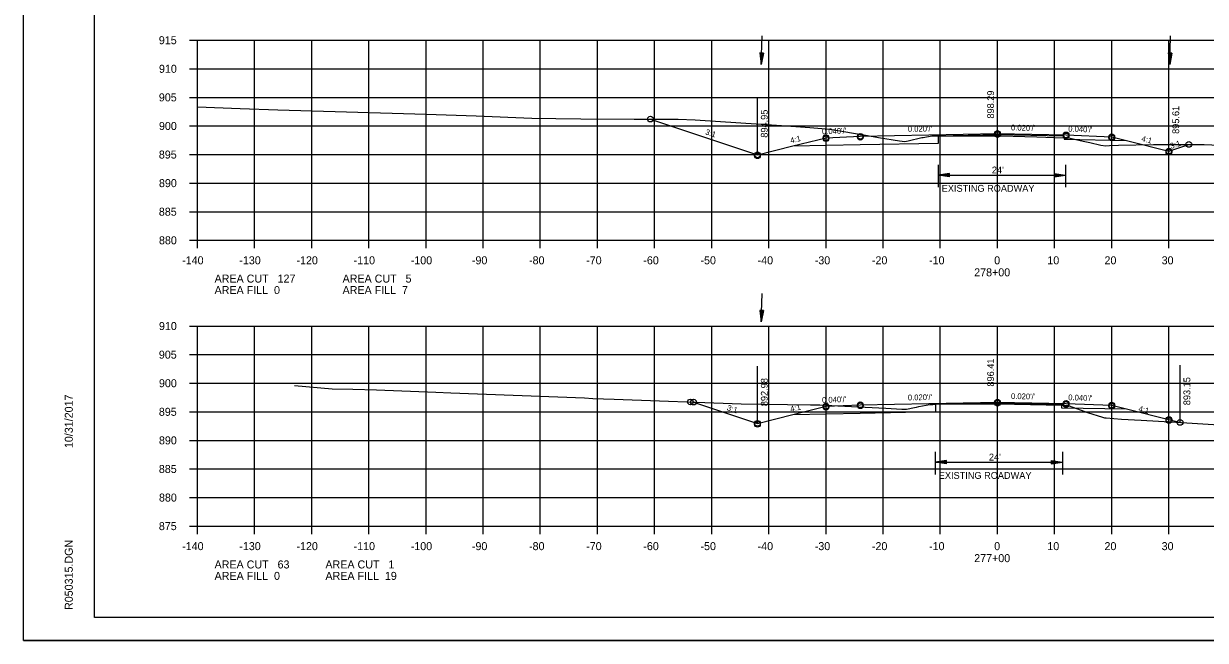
# Model space of a CAD drawing. Extents: x 1486524 to 1499135, y 326561 to 337924.
# Drawn here: x 1488812.5 to 1489019.3, y 331285.9 to 331393.8 of the extents above; entities that cross this region are included whole.
import ezdxf

# ---------------------------------------------------------------- set-up
doc = ezdxf.new("R2010")
doc.units = 0
for name, color, linetype in [('E_Const Align', 7, 'Continuous'), ('E_Const Align Station', 7, 'Continuous'), ('E_Ownership Information', 7, 'Continuous'), ('E_Property Line', 7, 'Continuous'), ('E_Proposed ROW and Easements', 7, 'Continuous'), ('E_Proposed ROW Fig Annot', 7, 'Continuous'), ('E_Quarter Calls', 7, 'Continuous'), ('E_Survey Point', 7, 'Continuous'), ('E_Title Sheet', 7, 'Continuous'), ('E_Tract Number', 7, 'Continuous'), ('R_Water Annot', 7, 'Continuous'), ('R_Xsect Elev', 7, 'Continuous'), ('R_Xsect Slope', 7, 'Continuous')]:
    doc.layers.add(name, color=color, linetype=linetype)

msp = doc.modelspace()

# ---------------------------------------------------------------- linework, layer by layer
at = {"layer": 'E_Const Align'}
for p, q in [((1488841.49, 331390.92), (1488842.89, 331390.92)), ((1488842.89, 331355.92), (1488842.89, 331390.92)), ((1488841.49, 331385.92), (1488842.89, 331385.92)), ((1488841.49, 331380.92), (1488842.89, 331380.92)), ((1488841.49, 331375.92), (1488842.89, 331375.92)), ((1488841.49, 331370.92), (1488842.89, 331370.92)), ((1488841.49, 331365.92), (1488842.89, 331365.92)), ((1488841.49, 331360.92), (1488842.89, 331360.92)), ((1488841.49, 331355.92), (1488842.89, 331355.92)), ((1488842.89, 331355.92), (1489122.89, 331355.92)), ((1488842.89, 331354.52), (1488842.89, 331355.92)), ((1488852.89, 331354.52), (1488852.89, 331355.92)), ((1488862.89, 331354.52), (1488862.89, 331355.92)), ((1488872.89, 331354.52), (1488872.89, 331355.92)), ((1488882.89, 331354.52), (1488882.89, 331355.92)), ((1488892.89, 331354.52), (1488892.89, 331355.92)), ((1488902.89, 331354.52), (1488902.89, 331355.92)), ((1488912.89, 331354.52), (1488912.89, 331355.92)), ((1488922.89, 331354.52), (1488922.89, 331355.92)), ((1488932.89, 331354.52), (1488932.89, 331355.92)), ((1488942.89, 331354.52), (1488942.89, 331355.92)), ((1488952.89, 331354.52), (1488952.89, 331355.92)), ((1488962.89, 331354.52), (1488962.89, 331355.92)), ((1488972.89, 331354.52), (1488972.89, 331355.92)), ((1488982.89, 331354.52), (1488982.89, 331355.92)), ((1488992.89, 331354.52), (1488992.89, 331355.92)), ((1489002.89, 331354.52), (1489002.89, 331355.92)), ((1489012.89, 331354.52), (1489012.89, 331355.92)), ((1488841.49, 331340.92), (1488842.89, 331340.92)), ((1488842.89, 331305.92), (1488842.89, 331340.92)), ((1488841.49, 331335.92), (1488842.89, 331335.92)), ((1488841.49, 331330.92), (1488842.89, 331330.92)), ((1488841.49, 331325.92), (1488842.89, 331325.92)), ((1488841.49, 331320.92), (1488842.89, 331320.92)), ((1488841.49, 331315.92), (1488842.89, 331315.92)), ((1488841.49, 331310.92), (1488842.89, 331310.92)), ((1488841.49, 331305.92), (1488842.89, 331305.92)), ((1488842.89, 331305.92), (1489122.89, 331305.92)), ((1488842.89, 331304.52), (1488842.89, 331305.92)), ((1488852.89, 331304.52), (1488852.89, 331305.92)), ((1488862.89, 331304.52), (1488862.89, 331305.92)), ((1488872.89, 331304.52), (1488872.89, 331305.92)), ((1488882.89, 331304.52), (1488882.89, 331305.92)), ((1488892.89, 331304.52), (1488892.89, 331305.92)), ((1488902.89, 331304.52), (1488902.89, 331305.92)), ((1488912.89, 331304.52), (1488912.89, 331305.92)), ((1488922.89, 331304.52), (1488922.89, 331305.92)), ((1488932.89, 331304.52), (1488932.89, 331305.92)), ((1488942.89, 331304.52), (1488942.89, 331305.92)), ((1488952.89, 331304.52), (1488952.89, 331305.92)), ((1488962.89, 331304.52), (1488962.89, 331305.92)), ((1488972.89, 331304.52), (1488972.89, 331305.92)), ((1488982.89, 331304.52), (1488982.89, 331305.92)), ((1488992.89, 331304.52), (1488992.89, 331305.92)), ((1489002.89, 331304.52), (1489002.89, 331305.92)), ((1489012.89, 331304.52), (1489012.89, 331305.92))]:
    msp.add_line(p, q, dxfattribs=at)
at = {"layer": 'E_Ownership Information'}
for p, q in [((1488842.89, 331390.92), (1489122.89, 331390.92)), ((1488842.89, 331355.92), (1488842.89, 331390.92)), ((1488852.89, 331355.92), (1488852.89, 331390.92)), ((1488862.89, 331355.92), (1488862.89, 331390.92)), ((1488872.89, 331355.92), (1488872.89, 331390.92)), ((1488882.89, 331355.92), (1488882.89, 331390.92)), ((1488892.89, 331355.92), (1488892.89, 331390.92)), ((1488902.89, 331355.92), (1488902.89, 331390.92)), ((1488912.89, 331355.92), (1488912.89, 331390.92)), ((1488922.89, 331355.92), (1488922.89, 331390.92)), ((1488932.89, 331355.92), (1488932.89, 331390.92)), ((1488942.89, 331355.92), (1488942.89, 331390.92)), ((1488952.89, 331355.92), (1488952.89, 331390.92)), ((1488962.89, 331355.92), (1488962.89, 331390.92)), ((1488972.89, 331355.92), (1488972.89, 331390.92)), ((1488982.89, 331355.92), (1488982.89, 331390.92)), ((1488992.89, 331355.92), (1488992.89, 331390.92)), ((1489002.89, 331355.92), (1489002.89, 331390.92)), ((1489012.89, 331355.92), (1489012.89, 331390.92)), ((1488842.89, 331385.92), (1489122.89, 331385.92)), ((1488842.89, 331380.92), (1489122.89, 331380.92)), ((1488842.89, 331375.92), (1489122.89, 331375.92)), ((1488842.89, 331370.92), (1489122.89, 331370.92)), ((1488842.89, 331365.92), (1489122.89, 331365.92)), ((1488842.89, 331360.92), (1489122.89, 331360.92)), ((1488842.89, 331355.92), (1489122.89, 331355.92)), ((1488842.89, 331340.92), (1489122.89, 331340.92)), ((1488842.89, 331305.92), (1488842.89, 331340.92)), ((1488852.89, 331305.92), (1488852.89, 331340.92)), ((1488862.89, 331305.92), (1488862.89, 331340.92)), ((1488872.89, 331305.92), (1488872.89, 331340.92)), ((1488882.89, 331305.92), (1488882.89, 331340.92)), ((1488892.89, 331305.92), (1488892.89, 331340.92)), ((1488902.89, 331305.92), (1488902.89, 331340.92)), ((1488912.89, 331305.92), (1488912.89, 331340.92)), ((1488922.89, 331305.92), (1488922.89, 331340.92)), ((1488932.89, 331305.92), (1488932.89, 331340.92)), ((1488942.89, 331305.92), (1488942.89, 331340.92)), ((1488952.89, 331305.92), (1488952.89, 331340.92)), ((1488962.89, 331305.92), (1488962.89, 331340.92)), ((1488972.89, 331305.92), (1488972.89, 331340.92)), ((1488982.89, 331305.92), (1488982.89, 331340.92)), ((1488992.89, 331305.92), (1488992.89, 331340.92)), ((1489002.89, 331305.92), (1489002.89, 331340.92)), ((1489012.89, 331305.92), (1489012.89, 331340.92)), ((1488842.89, 331335.92), (1489122.89, 331335.92)), ((1488842.89, 331330.92), (1489122.89, 331330.92)), ((1488842.89, 331325.92), (1489122.89, 331325.92)), ((1488842.89, 331320.92), (1489122.89, 331320.92)), ((1488842.89, 331315.92), (1489122.89, 331315.92)), ((1488842.89, 331310.92), (1489122.89, 331310.92)), ((1488842.89, 331305.92), (1489122.89, 331305.92))]:
    msp.add_line(p, q, dxfattribs=at)
at = {"layer": 'E_Property Line'}
for p, q in [((1488824.89, 331289.92), (1488824.89, 331495.38)), ((1488824.89, 331289.92), (1488824.89, 331289.92)), ((1489141.07, 331289.92), (1488824.89, 331289.92))]:
    msp.add_line(p, q, dxfattribs=at)
at = {"layer": 'E_Proposed ROW and Easements'}
for p, q in [((1488972.52, 331369.13), (1488972.52, 331365.2)), ((1488994.8, 331369.13), (1488994.8, 331365.2)), ((1488974.52, 331367.61), (1488972.52, 331367.31)), ((1488974.52, 331367.01), (1488972.52, 331367.31)), ((1488974.52, 331367.56), (1488972.86, 331367.31)), ((1488974.52, 331367.06), (1488972.86, 331367.31)), ((1488974.52, 331367.51), (1488973.2, 331367.31)), ((1488974.52, 331367.11), (1488973.2, 331367.31)), ((1488974.52, 331367.46), (1488973.53, 331367.31)), ((1488974.52, 331367.16), (1488973.53, 331367.31)), ((1488974.52, 331367.41), (1488973.87, 331367.31)), ((1488974.52, 331367.22), (1488973.87, 331367.31)), ((1488974.52, 331367.36), (1488974.21, 331367.31)), ((1488974.52, 331367.27), (1488974.21, 331367.31)), ((1488974.52, 331367.01), (1488974.52, 331367.61)), ((1488992.8, 331367.62), (1488994.8, 331367.32)), ((1488992.8, 331367.62), (1488992.8, 331367.02)), ((1488992.8, 331367.57), (1488994.47, 331367.32)), ((1488992.8, 331367.52), (1488994.12, 331367.32)), ((1488992.8, 331367.47), (1488993.79, 331367.32)), ((1488992.8, 331367.41), (1488993.45, 331367.32)), ((1488992.8, 331367.36), (1488993.12, 331367.32)), ((1488992.8, 331367.02), (1488994.8, 331367.32)), ((1488992.8, 331367.22), (1488993.45, 331367.32)), ((1488992.8, 331367.12), (1488994.12, 331367.32)), ((1488992.8, 331367.07), (1488994.47, 331367.32)), ((1488992.8, 331367.17), (1488993.79, 331367.32)), ((1488992.8, 331367.27), (1488993.12, 331367.32)), ((1488972, 331318.91), (1488972, 331314.98)), ((1488994.28, 331318.91), (1488994.28, 331314.98)), ((1488974, 331317.39), (1488972, 331317.09)), ((1488974, 331316.79), (1488972, 331317.09)), ((1488974, 331317.34), (1488972.34, 331317.09)), ((1488974, 331316.84), (1488972.34, 331317.09)), ((1488974, 331317.29), (1488972.68, 331317.09)), ((1488974, 331316.89), (1488972.68, 331317.09)), ((1488974, 331317.24), (1488973.01, 331317.09)), ((1488974, 331316.94), (1488973.01, 331317.09)), ((1488974, 331317.19), (1488973.35, 331317.09)), ((1488974, 331317), (1488973.35, 331317.09)), ((1488974, 331317.14), (1488973.69, 331317.09)), ((1488974, 331317.05), (1488973.69, 331317.09)), ((1488974, 331316.79), (1488974, 331317.39)), ((1488992.28, 331317.4), (1488994.28, 331317.1)), ((1488992.28, 331317.4), (1488992.28, 331316.8)), ((1488992.28, 331317.35), (1488993.94, 331317.1)), ((1488992.28, 331317.3), (1488993.6, 331317.1)), ((1488992.28, 331317.25), (1488993.27, 331317.1)), ((1488992.28, 331317.19), (1488992.93, 331317.1)), ((1488992.28, 331317.14), (1488992.59, 331317.1)), ((1488992.28, 331316.8), (1488994.28, 331317.1)), ((1488992.28, 331317), (1488992.93, 331317.1)), ((1488992.28, 331316.9), (1488993.6, 331317.1)), ((1488992.28, 331316.85), (1488993.94, 331317.1)), ((1488992.28, 331316.95), (1488993.27, 331317.1)), ((1488992.28, 331317.05), (1488992.59, 331317.1))]:
    msp.add_line(p, q, dxfattribs=at)
at = {"layer": 'E_Proposed ROW Fig Annot'}
for p, q in [((1488941.32, 331388.7), (1488941.55, 331386.69)), ((1488941.92, 331388.68), (1488941.32, 331388.7)), ((1488941.32, 331388.7), (1488941.55, 331386.69)), ((1488941.92, 331388.68), (1488941.32, 331388.7)), ((1488941.37, 331388.69), (1488941.56, 331387.02)), ((1488941.37, 331388.69), (1488941.56, 331387.02)), ((1488941.42, 331388.69), (1488941.57, 331387.36)), ((1488941.42, 331388.69), (1488941.57, 331387.36)), ((1488941.47, 331388.69), (1488941.58, 331387.7)), ((1488941.47, 331388.69), (1488941.58, 331387.7)), ((1488941.52, 331388.69), (1488941.6, 331388.04)), ((1488941.52, 331388.69), (1488941.6, 331388.04)), ((1488941.92, 331388.68), (1488941.55, 331386.69)), ((1488941.92, 331388.68), (1488941.55, 331386.69)), ((1488941.87, 331388.68), (1488941.56, 331387.02)), ((1488941.87, 331388.68), (1488941.56, 331387.02)), ((1488941.57, 331388.69), (1488941.61, 331388.37)), ((1488941.57, 331388.69), (1488941.61, 331388.37)), ((1488941.81, 331388.68), (1488941.57, 331387.36)), ((1488941.81, 331388.68), (1488941.57, 331387.36)), ((1488941.76, 331388.68), (1488941.58, 331387.7)), ((1488941.76, 331388.68), (1488941.58, 331387.7)), ((1488941.71, 331388.68), (1488941.6, 331388.04)), ((1488941.71, 331388.68), (1488941.6, 331388.04)), ((1488941.66, 331388.68), (1488941.61, 331388.37)), ((1488941.66, 331388.68), (1488941.61, 331388.37)), ((1489012.79, 331388.7), (1489013.03, 331386.69)), ((1489013.39, 331388.68), (1489012.79, 331388.7)), ((1489012.79, 331388.7), (1489013.03, 331386.69)), ((1489013.39, 331388.68), (1489012.79, 331388.7)), ((1489012.84, 331388.69), (1489013.04, 331387.02)), ((1489012.84, 331388.69), (1489013.04, 331387.02)), ((1489012.89, 331388.69), (1489013.05, 331387.36)), ((1489012.89, 331388.69), (1489013.05, 331387.36)), ((1489012.94, 331388.69), (1489013.06, 331387.7)), ((1489012.94, 331388.69), (1489013.06, 331387.7)), ((1489012.99, 331388.69), (1489013.07, 331388.04)), ((1489012.99, 331388.69), (1489013.07, 331388.04)), ((1489013.39, 331388.68), (1489013.03, 331386.69)), ((1489013.39, 331388.68), (1489013.03, 331386.69)), ((1489013.04, 331388.69), (1489013.08, 331388.37)), ((1489013.04, 331388.69), (1489013.08, 331388.37)), ((1489013.34, 331388.68), (1489013.04, 331387.02)), ((1489013.34, 331388.68), (1489013.04, 331387.02)), ((1489013.29, 331388.68), (1489013.05, 331387.36)), ((1489013.29, 331388.68), (1489013.05, 331387.36)), ((1489013.24, 331388.68), (1489013.06, 331387.7)), ((1489013.24, 331388.68), (1489013.06, 331387.7)), ((1489013.19, 331388.68), (1489013.07, 331388.04)), ((1489013.19, 331388.68), (1489013.07, 331388.04)), ((1489013.14, 331388.68), (1489013.08, 331388.37)), ((1489013.14, 331388.68), (1489013.08, 331388.37)), ((1488972.52, 331367.31), (1488994.8, 331367.32)), ((1488941.32, 331343.65), (1488941.55, 331341.64)), ((1488941.92, 331343.63), (1488941.32, 331343.65)), ((1488941.32, 331343.65), (1488941.55, 331341.64)), ((1488941.92, 331343.63), (1488941.32, 331343.65)), ((1488941.37, 331343.65), (1488941.56, 331341.98)), ((1488941.37, 331343.65), (1488941.56, 331341.98)), ((1488941.42, 331343.65), (1488941.57, 331342.32)), ((1488941.42, 331343.65), (1488941.57, 331342.32)), ((1488941.47, 331343.65), (1488941.58, 331342.65)), ((1488941.47, 331343.65), (1488941.58, 331342.65)), ((1488941.52, 331343.64), (1488941.6, 331342.99)), ((1488941.52, 331343.64), (1488941.6, 331342.99)), ((1488941.92, 331343.63), (1488941.55, 331341.64)), ((1488941.92, 331343.63), (1488941.55, 331341.64)), ((1488941.87, 331343.63), (1488941.56, 331341.98)), ((1488941.87, 331343.63), (1488941.56, 331341.98)), ((1488941.81, 331343.64), (1488941.57, 331342.32)), ((1488941.57, 331343.64), (1488941.61, 331343.33)), ((1488941.81, 331343.64), (1488941.57, 331342.32)), ((1488941.57, 331343.64), (1488941.61, 331343.33)), ((1488941.76, 331343.64), (1488941.58, 331342.65)), ((1488941.76, 331343.64), (1488941.58, 331342.65)), ((1488941.71, 331343.64), (1488941.6, 331342.99)), ((1488941.71, 331343.64), (1488941.6, 331342.99)), ((1488941.66, 331343.64), (1488941.61, 331343.33)), ((1488941.66, 331343.64), (1488941.61, 331343.33)), ((1488972, 331317.09), (1488994.28, 331317.1))]:
    msp.add_line(p, q, dxfattribs=at)
at = {"layer": 'E_Quarter Calls'}
msp.add_line((1488812.48, 331285.94), (1489145.82, 331285.94), dxfattribs=at)
for points in [[(1488812.48, 331499.28), (1489145.82, 331499.28), (1489145.82, 331285.94), (1488812.48, 331285.94)], [(1489058.81, 331495.38), (1489058.81, 331485.5), (1489094.54, 331485.5), (1489094.54, 331482.58), (1489117.74, 331482.58), (1489117.74, 331458.25), (1489141.07, 331458.25), (1489141.07, 331289.92), (1488824.89, 331289.92), (1488824.89, 331495.38)]]:
    msp.add_lwpolyline(points, close=True, dxfattribs=at)
for centre in [(1488922.16, 331377.12), (1488922.16, 331377.12), (1488982.89, 331374.59), (1488982.89, 331374.59), (1488982.89, 331374.42), (1488994.89, 331374.35), (1488994.89, 331374.35), (1488952.89, 331373.87), (1488952.89, 331373.87), (1488952.89, 331373.7), (1488958.89, 331374.11), (1488958.89, 331374.11), (1488958.89, 331373.94), (1488994.89, 331374.18), (1489002.89, 331374.03), (1489002.89, 331374.03), (1489002.89, 331373.86), (1489016.38, 331372.7), (1489016.38, 331372.7), (1488940.89, 331370.87), (1488940.89, 331370.87), (1488940.89, 331370.7), (1489012.89, 331371.53), (1489012.89, 331371.53), (1489012.89, 331371.36), (1488929.15, 331327.64), (1488929.72, 331327.62), (1488929.72, 331327.62), (1488952.89, 331326.9), (1488952.89, 331326.9), (1488952.89, 331326.73), (1488958.89, 331327.14), (1488958.89, 331327.14), (1488958.89, 331326.97), (1488982.89, 331327.62), (1488982.89, 331327.62), (1488982.89, 331327.45), (1488994.89, 331327.38), (1488994.89, 331327.38), (1488994.89, 331327.21), (1489002.89, 331327.06), (1489002.89, 331327.06), (1489002.89, 331326.89), (1488940.89, 331323.9), (1488940.89, 331323.9), (1488940.89, 331323.73), (1489012.89, 331324.56), (1489012.89, 331324.56), (1489012.89, 331324.39), (1489014.84, 331324.07), (1489014.84, 331324.07)]:
    msp.add_circle(centre, 0.5, dxfattribs=at)
at = {"layer": 'E_Survey Point'}
for points in [[(1488947.06, 331372.42), (1488958.89, 331372.65), (1488972.59, 331372.93), (1488972.59, 331374.22), (1488982.89, 331374.43), (1488994.53, 331374.19), (1488994.54, 331373.61), (1489005.45, 331373.39)], [(1488947.06, 331325.44), (1488958.89, 331325.68), (1488972.13, 331325.95), (1488972.13, 331327.24), (1488982.89, 331327.45), (1488994.09, 331327.23), (1488994.1, 331326.64), (1489005.45, 331326.42)]]:
    msp.add_lwpolyline(points, dxfattribs=at)
at = {"layer": 'E_Title Sheet'}
for points in [[(1488922.16, 331377.12), (1488940.89, 331370.87), (1488947.06, 331372.42), (1488952.89, 331373.87), (1488958.89, 331374.11), (1488982.89, 331374.59), (1488994.89, 331374.35), (1489002.89, 331374.03), (1489005.45, 331373.39), (1489012.89, 331371.53), (1489016.38, 331372.7)], [(1488929.72, 331327.62), (1488940.89, 331323.9), (1488947.06, 331325.44), (1488952.89, 331326.9), (1488958.89, 331327.14), (1488982.89, 331327.62), (1488994.89, 331327.38), (1489002.89, 331327.06), (1489005.45, 331326.42), (1489012.89, 331324.56), (1489014.84, 331324.07)]]:
    msp.add_lwpolyline(points, dxfattribs=at)
at = {"layer": 'E_Tract Number'}
for points in [[(1488842.89, 331379.25), (1488850.35, 331379), (1488856.96, 331378.77), (1488868.95, 331378.41), (1488882.91, 331378.01), (1488891.69, 331377.71), (1488901.38, 331377.27), (1488905.62, 331377.2), (1488909.96, 331377.18), (1488919.31, 331377.13), (1488927.04, 331377.09), (1488929.99, 331376.97), (1488945.09, 331376.02), (1488950.07, 331375.68), (1488953.57, 331375.38), (1488960.15, 331374.23), (1488962.09, 331373.89), (1488965.75, 331373.33), (1488966.7, 331373.18), (1488967.24, 331373.33), (1488969.67, 331373.88), (1488969.91, 331373.92), (1488971.42, 331374.2), (1488972.01, 331374.2), (1488972.59, 331374.22), (1488978.52, 331374.2), (1488983.56, 331374.22), (1488989.78, 331374), (1488994.53, 331373.85), (1488995.16, 331373.82), (1488995.63, 331373.79), (1488997.86, 331373.27), (1488999.08, 331373.01), (1489000.99, 331372.57), (1489001.86, 331372.42), (1489002.51, 331372.48), (1489004.1, 331372.59), (1489010.22, 331372.69), (1489019.04, 331372.7), (1489031.33, 331372.15)], [(1488859.88, 331330.5), (1488866.47, 331329.93), (1488870.11, 331329.88), (1488874.2, 331329.78), (1488884.62, 331329.37), (1488887.25, 331329.26), (1488910.62, 331328.34), (1488912.06, 331328.24), (1488915.81, 331328.13), (1488938.06, 331327.32), (1488950.15, 331327.14), (1488951.83, 331327.12), (1488954.93, 331326.98), (1488963.36, 331326.55), (1488966.17, 331326.4), (1488966.99, 331326.36), (1488968.4, 331326.68), (1488968.74, 331326.74), (1488969.14, 331326.82), (1488971.08, 331327.19), (1488971.56, 331327.21), (1488972.13, 331327.23), (1488977.94, 331327.29), (1488983.09, 331327.34), (1488988.67, 331327.21), (1488994.09, 331327.09), (1488994.72, 331327.06), (1488995.29, 331327.03), (1488998.18, 331325.98), (1488998.65, 331325.82), (1489001.27, 331324.97), (1489001.61, 331324.87), (1489001.91, 331324.85), (1489004.61, 331324.66), (1489008.03, 331324.47), (1489015.12, 331324.05), (1489033.76, 331322.89)]]:
    msp.add_lwpolyline(points, dxfattribs=at)
at = {"layer": 'R_Water Annot'}
for p, q in [((1488941.55, 331386.69), (1488941.71, 331391.68)), ((1489013.03, 331386.69), (1489013.18, 331391.68)), ((1488941.55, 331341.64), (1488941.71, 331346.64))]:
    msp.add_line(p, q, dxfattribs=at)
at = {"layer": 'R_Xsect Elev'}
for p, q in [((1488982.89, 331374.21), (1488982.89, 331384.21)), ((1489012.89, 331371.53), (1489012.89, 331381.53)), ((1488940.89, 331370.87), (1488940.89, 331380.87)), ((1488982.89, 331327.33), (1488982.89, 331337.33)), ((1488940.89, 331323.9), (1488940.89, 331333.9)), ((1489014.84, 331324.07), (1489014.84, 331334.07))]:
    msp.add_line(p, q, dxfattribs=at)

# ---------------------------------------------------------------- texts
at = {"layer": 'E_Const Align Station'}
for s, p in [('915', (1488836.14, 331390.22)), ('910', (1488836.16, 331385.22)), ('905', (1488836.14, 331380.22)), ('900', (1488836.16, 331375.22)), ('895', (1488836.14, 331370.22)), ('890', (1488836.16, 331365.22)), ('885', (1488836.14, 331360.22)), ('880', (1488836.16, 331355.22)), ('-140', (1488840.22, 331351.72)), ('-130', (1488850.22, 331351.72)), ('-120', (1488860.22, 331351.72)), ('-110', (1488870.22, 331351.72)), ('-100', (1488880.22, 331351.72)), ('-90', (1488890.92, 331351.72)), ('-80', (1488900.92, 331351.72)), ('-70', (1488910.92, 331351.72)), ('-60', (1488920.92, 331351.72)), ('-50', (1488930.92, 331351.72)), ('-40', (1488940.92, 331351.72)), ('-30', (1488950.92, 331351.72)), ('-20', (1488960.92, 331351.72)), ('-10', (1488970.92, 331351.72)), ('0', (1488982.32, 331351.72)), ('10', (1488991.62, 331351.72)), ('20', (1489001.62, 331351.72)), ('30', (1489011.62, 331351.72)), ('AREA CUT   127', (1488845.89, 331348.52)), ('AREA CUT   5', (1488868.29, 331348.52)), ('278+00', (1488978.82, 331349.62)), ('AREA FILL  0', (1488845.89, 331346.52)), ('AREA FILL  7', (1488868.29, 331346.52)), ('910', (1488836.16, 331340.22)), ('905', (1488836.14, 331335.22)), ('900', (1488836.16, 331330.22)), ('895', (1488836.14, 331325.22)), ('890', (1488836.16, 331320.22)), ('885', (1488836.14, 331315.22)), ('880', (1488836.16, 331310.22)), ('875', (1488836.14, 331305.22)), ('-140', (1488840.22, 331301.72)), ('-130', (1488850.22, 331301.72)), ('-120', (1488860.22, 331301.72)), ('-110', (1488870.22, 331301.72)), ('-100', (1488880.22, 331301.72)), ('-90', (1488890.92, 331301.72)), ('-80', (1488900.92, 331301.72)), ('-70', (1488910.92, 331301.72)), ('-60', (1488920.92, 331301.72)), ('-50', (1488930.92, 331301.72)), ('-40', (1488940.92, 331301.72)), ('-30', (1488950.92, 331301.72)), ('-20', (1488960.92, 331301.72)), ('-10', (1488970.92, 331301.72)), ('0', (1488982.32, 331301.72)), ('10', (1488991.62, 331301.72)), ('20', (1489001.62, 331301.72)), ('30', (1489011.62, 331301.72)), ('277+00', (1488978.82, 331299.62)), ('AREA CUT   63', (1488845.89, 331298.52)), ('     AREA CUT   1', (1488862.69, 331298.52)), ('AREA FILL  0', (1488845.89, 331296.52)), ('     AREA FILL  19', (1488862.69, 331296.52))]:
    msp.add_text(s, height=1.4, dxfattribs=at).set_placement(p)
at = {"layer": 'E_Property Line'}
for s, p in [('10/31/2017', (1488821.08, 331319.57)), ('R050315.DGN', (1488821.08, 331291.25))]:
    msp.add_text(s, height=1.4, rotation=90, dxfattribs=at).set_placement(p)
at = {"layer": 'E_Proposed ROW Fig Annot'}
for s, p in [("24'", (1488981.91, 331367.62)), ('EXISTING ROADWAY', (1488973.14, 331364.41)), ("24'", (1488981.39, 331317.4)), ('EXISTING ROADWAY', (1488972.62, 331314.19))]:
    msp.add_text(s, height=1.2, dxfattribs=at).set_placement(p)
at = {"layer": 'R_Xsect Elev'}
for s, p in [('898.29', (1488982.29, 331377.21)), ('895.61', (1489014.69, 331374.53)), ('894.95', (1488942.69, 331373.87)), ('896.41', (1488982.29, 331330.33)), ('892.98', (1488942.69, 331326.9)), ('893.15', (1489016.64, 331327.07))]:
    msp.add_text(s, height=1.2, rotation=90, dxfattribs=at).set_placement(p)
at = {"layer": 'R_Xsect Slope'}
for s, rotation, p in [('3:1', 341.5651, (1488931.68, 331374.47)), ("0.040'/'", 2.2906, (1488952.21, 331374.45)), ("0.020'/'", 1.1458, (1488967.22, 331374.88)), ("0.020'/'", 358.8542, (1488985.25, 331375.15)), ("0.040'/'", 357.7094, (1488995.26, 331374.94)), ('4:1', 14.0362, (1488946.76, 331372.86)), ('4:1', 345.9638, (1489008.01, 331373.27)), ('3:1', 18.4349, (1489013.28, 331371.89)), ('4:1', 14.0362, (1488946.76, 331325.88)), ("0.040'/'", 2.2906, (1488952.21, 331327.47)), ("0.020'/'", 1.1458, (1488967.22, 331327.91)), ("0.020'/'", 358.8542, (1488985.25, 331328.17)), ("0.040'/'", 357.7094, (1488995.26, 331327.96)), ('3:1', 341.5651, (1488935.46, 331326.23)), ('4:1', 345.9638, (1489007.49, 331326.02))]:
    msp.add_text(s, height=1, rotation=rotation, dxfattribs=at).set_placement(p)

doc.saveas('drawing.dxf')
